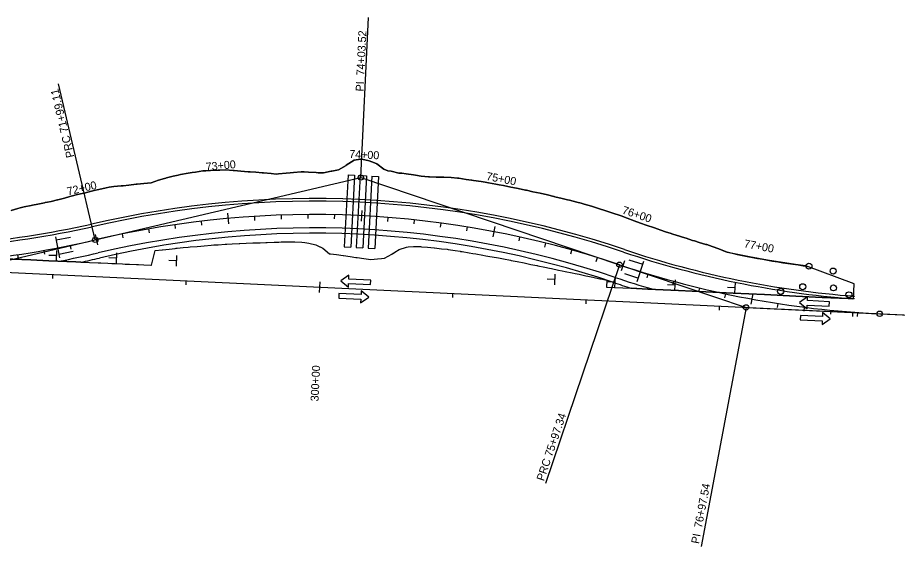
# Model space of a CAD drawing. Extents: x 1140339 to 1165793, y 1646213 to 1669071.
# Drawn here: x 1164666 to 1165325, y 1656552 to 1656948 of the extents above; entities that cross this region are included whole.
import ezdxf

# ---------------------------------------------------------------- set-up
doc = ezdxf.new("R2010")
doc.units = 0
for name, color, linetype in [('Level 47', 7, 'Continuous'), ('R_Horz Alg', 7, 'Continuous'), ('R_Horz Alg Annot', 7, 'Continuous'), ('R_MOT', 7, 'Continuous'), ('R_No Plot', 7, 'Continuous'), ('R_Proposed Const Limits_Fill', 7, 'Continuous'), ('R_Proposed Road_Lane', 7, 'Continuous'), ('R_Proposed Road_Shoulder', 7, 'Continuous'), ('R_Water', 7, 'Continuous')]:
    doc.layers.add(name, color=color, linetype=linetype)

msp = doc.modelspace()

# ---------------------------------------------------------------- linework, layer by layer
at = {"layer": 'Level 47'}
for centre in [(1165258.51, 1656761.83), (1165276.59, 1656758.13), (1165237.3, 1656742.92), (1165253.81, 1656746.4), (1165276.88, 1656745.53), (1165288.44, 1656740.36)]:
    msp.add_circle(centre, 2.25, dxfattribs=at)
at = {"layer": 'R_Horz Alg'}
for p, q in [((1164092.75, 1656783.95), (1165790.84, 1656703.38)), ((1165311.49, 1656726.12), (1165424.02, 1656720.78))]:
    msp.add_line(p, q, dxfattribs=at)
for centre, start, end in [((1164887.48, 1656084.3), 71.35438, 103.21228), ((1164560.09, 1657478.78), 267.28333, 283.21228), ((1165345.43, 1657441.51), 251.35438, 267.28333)]:
    msp.add_arc(centre, 716.2, start, end, dxfattribs=at)
at = {"layer": 'R_Horz Alg Annot'}
for p, q in [((1164723.78, 1656781.54), (1164922.78, 1656828.26)), ((1164922.78, 1656828.26), (1165116.46, 1656762.91)), ((1164626.23, 1656758.64), (1164723.78, 1656781.54)), ((1165116.46, 1656762.91), (1165211.4, 1656730.87)), ((1165211.4, 1656730.87), (1165311.49, 1656726.12))]:
    msp.add_line(p, q, dxfattribs=at)
for points in [[(1164922.78, 1656828.26), (1164928.47, 1656948.12)], [(1164723.78, 1656781.54), (1164696.36, 1656898.36)], [(1164923.4, 1656803.6), (1164923, 1656795.61)], [(1164822.94, 1656801.6), (1164823.66, 1656793.63)], [(1164843.43, 1656796.13), (1164843.24, 1656799.13)], [(1164863.32, 1656797.09), (1164863.22, 1656800.09)], [(1164883.23, 1656797.48), (1164883.21, 1656800.48)], [(1164903.15, 1656797.32), (1164903.21, 1656800.32)], [(1164942.92, 1656795.34), (1164943.16, 1656798.33)], [(1164962.76, 1656793.51), (1164963.07, 1656796.5)], [(1164764.35, 1656786.79), (1164763.84, 1656789.74)], [(1164784.02, 1656789.95), (1164783.58, 1656792.92)], [(1164803.76, 1656792.57), (1164803.41, 1656795.54)], [(1164982.53, 1656791.13), (1164982.93, 1656794.11)], [(1165002.23, 1656788.2), (1165002.71, 1656791.17)], [(1165023.16, 1656791.6), (1165021.65, 1656783.74)], [(1164723.74, 1656785.64), (1164725.56, 1656777.85)], [(1164744.79, 1656783.08), (1164744.19, 1656786.02)], [(1165041.34, 1656780.7), (1165041.99, 1656783.63)], [(1164705.73, 1656774.48), (1164705.12, 1656777.42)], [(1165060.73, 1656776.13), (1165061.45, 1656779.04)], [(1164666.19, 1656767.45), (1164665.75, 1656770.42)], [(1164686.01, 1656770.69), (1164685.48, 1656773.64)], [(1165079.98, 1656771.03), (1165080.79, 1656773.92)], [(1165116.46, 1656762.91), (1165061.11, 1656598.88)], [(1165099.08, 1656765.38), (1165099.97, 1656768.25)], [(1165120.25, 1656765.85), (1165117.72, 1656758.26)], [(1164691.93, 1656752.52), (1164692.07, 1656755.51)], [(1164791.82, 1656747.78), (1164791.96, 1656750.77)], [(1164892.04, 1656750.03), (1164891.66, 1656742.04)], [(1165137.17, 1656753.13), (1165138.04, 1656756)], [(1165156.48, 1656747.58), (1165157.26, 1656750.48)], [(1165175.93, 1656742.58), (1165176.63, 1656745.49)], [(1164991.59, 1656738.3), (1164991.74, 1656741.29)], [(1165091.48, 1656733.56), (1165091.62, 1656736.55)], [(1165195.51, 1656738.12), (1165196.13, 1656741.05)], [(1165216.47, 1656741.09), (1165215.02, 1656733.22)], [(1165211.4, 1656730.87), (1165177.62, 1656551.76)], [(1165191.37, 1656728.82), (1165191.51, 1656731.81)], [(1165235, 1656730.84), (1165235.47, 1656733.81)], [(1165254.89, 1656728.04), (1165255.27, 1656731.01)], [(1165274.85, 1656725.79), (1165275.14, 1656728.77)], [(1165291.26, 1656724.08), (1165291.4, 1656727.07)], [(1165294.86, 1656724.1), (1165295.07, 1656727.09)]]:
    msp.add_lwpolyline(points, dxfattribs=at)
for centre in [(1164922.78, 1656828.26), (1164723.78, 1656781.54), (1165116.46, 1656762.91), (1165211.4, 1656730.87), (1165311.49, 1656726.12)]:
    msp.add_circle(centre, 2, dxfattribs=at)
at = {"layer": 'R_MOT'}
for p, q in [((1164694.07, 1656783.87), (1164697.09, 1656768.16)), ((1164705.29, 1656783.34), (1164694.56, 1656781.28)), ((1164694.5, 1656769.68), (1164689.05, 1656769.9)), ((1164694.79, 1656773.65), (1164694.46, 1656765.66)), ((1164707.34, 1656772.68), (1164696.61, 1656770.62)), ((1164739.76, 1656771.84), (1164739.43, 1656763.85)), ((1164784.72, 1656769.88), (1164784.39, 1656761.89)), ((1164739.48, 1656767.87), (1164734.03, 1656768.1)), ((1164784.44, 1656765.91), (1164778.98, 1656766.13)), ((1165123.65, 1656766.6), (1165134.05, 1656763.25)), ((1165129.91, 1656750.41), (1165134.82, 1656765.64)), ((1165120.33, 1656756.27), (1165130.72, 1656752.92)), ((1165067.94, 1656751.78), (1165062.48, 1656752.01)), ((1165068.22, 1656755.75), (1165067.89, 1656747.76)), ((1165112.95, 1656749.92), (1165107.5, 1656750.15)), ((1165113.23, 1656753.89), (1165112.9, 1656745.9)), ((1165158.15, 1656751.65), (1165157.82, 1656743.65)), ((1165203.13, 1656749.58), (1165202.8, 1656741.58)), ((1165157.87, 1656747.68), (1165152.42, 1656747.9)), ((1165202.85, 1656745.6), (1165197.39, 1656745.83))]:
    msp.add_line(p, q, dxfattribs=at)
for points in [[(1164913.84, 1656754.97), (1164907.79, 1656750.75), (1164913.41, 1656745.98), (1164913.54, 1656748.78), (1164930.07, 1656748), (1164930.23, 1656751.37), (1164913.7, 1656752.16)], [(1164922.6, 1656734.27), (1164928.65, 1656738.49), (1164923.03, 1656743.26), (1164922.89, 1656740.45), (1164906.36, 1656741.23), (1164906.2, 1656737.86), (1164922.73, 1656737.08)], [(1165257.48, 1656738.77), (1165251.43, 1656734.55), (1165257.05, 1656729.78), (1165257.19, 1656732.59), (1165273.72, 1656731.8), (1165273.88, 1656735.17), (1165257.35, 1656735.96)], [(1165268.31, 1656717.99), (1165274.36, 1656722.21), (1165268.73, 1656726.98), (1165268.6, 1656724.17), (1165252.07, 1656724.95), (1165251.91, 1656721.58), (1165268.44, 1656720.8)]]:
    msp.add_lwpolyline(points, close=True, dxfattribs=at)
at = {"layer": 'R_No Plot'}
msp.add_line((1164947.09, 1656771.47), (1164947.12, 1656771.49), dxfattribs=at)
for points in [[(1165197.25, 1656772.27), (1165190.97, 1656774.87), (1165190.93, 1656774.89), (1165186.07, 1656776.65), (1165181.89, 1656777.93), (1165181.15, 1656778.16), (1165176.21, 1656779.58), (1165172.74, 1656780.68), (1165171.31, 1656781.14), (1165166.43, 1656782.74), (1165163.65, 1656783.59), (1165161.52, 1656784.21), (1165156.62, 1656785.75), (1165154.55, 1656786.42), (1165154.45, 1656786.46), (1165151.75, 1656787.35), (1165146.89, 1656788.98), (1165145.52, 1656789.46), (1165142.04, 1656790.67), (1165137.2, 1656792.34), (1165136.52, 1656792.58), (1165132.37, 1656794.05), (1165127.55, 1656795.77), (1165127.55, 1656795.77), (1165127.54, 1656795.77), (1165122.26, 1656797.77), (1165117.72, 1656799.43), (1165116.96, 1656799.7), (1165111.62, 1656801.54), (1165107.79, 1656802.85), (1165106.27, 1656803.36), (1165100.9, 1656805.11), (1165097.79, 1656806.02), (1165095.48, 1656806.72), (1165090.07, 1656808.35), (1165087.73, 1656809.04), (1165084.62, 1656809.83), (1165079.15, 1656811.22), (1165077.56, 1656811.63), (1165073.67, 1656812.6), (1165068.17, 1656813.88), (1165067.55, 1656814.02), (1165067.35, 1656814.07), (1165062.67, 1656815.16), (1165057.16, 1656816.41), (1165057.12, 1656816.42), (1165051.64, 1656817.62), (1165046.87, 1656818.65), (1165046.12, 1656818.81), (1165040.6, 1656819.97), (1165036.6, 1656820.8), (1165035.07, 1656821.11), (1165029.53, 1656822.23), (1165026.31, 1656822.86), (1165023.99, 1656823.3), (1165018.43, 1656824.32), (1165015.99, 1656824.75), (1165012.87, 1656825.27), (1165007.28, 1656826.09), (1165006.04, 1656826.27), (1165005.62, 1656826.33), (1165001.69, 1656826.88), (1164996.1, 1656827.65), (1164995.22, 1656827.76), (1164990.5, 1656828.35), (1164984.83, 1656828.55), (1164984.75, 1656828.55), (1164979.16, 1656828.61), (1164974.21, 1656828.65), (1164973.49, 1656828.65), (1164967.89, 1656829.25), (1164963.83, 1656830.02), (1164962.34, 1656830.29), (1164956.76, 1656831.13), (1164953.45, 1656831.42), (1164951.14, 1656831.62), (1164945.6, 1656833), (1164943.09, 1656833.31), (1164940.05, 1656834.6), (1164934.64, 1656838.59), (1164932.95, 1656839.35), (1164929.07, 1656840.82), (1164923.44, 1656842.08), (1164923.43, 1656842.07), (1164922.49, 1656841.92), (1164917.69, 1656841.17), (1164911.88, 1656837.41), (1164911.75, 1656837.29), (1164906.13, 1656834.12), (1164901.15, 1656833.13), (1164900.48, 1656832.99), (1164894.84, 1656831.73), (1164890.69, 1656831.8), (1164889.22, 1656831.89), (1164883.6, 1656832.24), (1164880.24, 1656832.44), (1164877.98, 1656832.47), (1164872.37, 1656832.01), (1164869.81, 1656831.77), (1164866.76, 1656831.47), (1164861.16, 1656830.9), (1164859.4, 1656830.86), (1164855.53, 1656831.16), (1164849.88, 1656831.76), (1164848.9, 1656831.86), (1164844.21, 1656832.33), (1164839.81, 1656832.51), (1164838.55, 1656832.56), (1164838.38, 1656832.57), (1164832.87, 1656833.01), (1164827.81, 1656833.47), (1164827.17, 1656833.53), (1164821.46, 1656834.02), (1164817.24, 1656833.8), (1164815.8, 1656833.74), (1164810.15, 1656833.46), (1164806.72, 1656833.27), (1164804.49, 1656833.14), (1164798.88, 1656832.37), (1164796.3, 1656831.89), (1164793.28, 1656831.5), (1164787.71, 1656830.47), (1164785.93, 1656830.11), (1164782.16, 1656829.33), (1164777.27, 1656828.01), (1164776.67, 1656827.82), (1164775.67, 1656827.62), (1164771.18, 1656826.36), (1164765.79, 1656824.33), (1164765.58, 1656824.32), (1164760.16, 1656823.85), (1164760.14, 1656823.85), (1164755.11, 1656823.38), (1164754.52, 1656823.32), (1164748.95, 1656822.45), (1164744.68, 1656822.09), (1164743.29, 1656821.97), (1164737.63, 1656821.45), (1164734.21, 1656820.93), (1164732.06, 1656820.5), (1164726.54, 1656819.26), (1164723.95, 1656818.66), (1164721.04, 1656817.97), (1164715.55, 1656816.63), (1164715.55, 1656816.63), (1164713.91, 1656816.25), (1164710.57, 1656815.47), (1164705.62, 1656814.16), (1164704.7, 1656813.91), (1164700.67, 1656812.87), (1164695.71, 1656811.6), (1164695.49, 1656811.54), (1164690.74, 1656810.39), (1164687.95, 1656809.8), (1164686.21, 1656809.44), (1164685.73, 1656809.34), (1164680.71, 1656808.33), (1164676.88, 1656807.58), (1164675.68, 1656807.35), (1164670.65, 1656806.38), (1164667.57, 1656805.55), (1164665.68, 1656805.05), (1164660.72, 1656803.55)], [(1164713.11, 1656764.79), (1164725.97, 1656764.29), (1164727.85, 1656764.22), (1164727.85, 1656764.22), (1164733.28, 1656763.99), (1164736.15, 1656763.86), (1164738.7, 1656763.75), (1164744.09, 1656763.52), (1164746.17, 1656763.42), (1164749.46, 1656763.28), (1164754.81, 1656763.05), (1164756.12, 1656762.99), (1164760.14, 1656762.81), (1164765.45, 1656762.58), (1164766, 1656762.56), (1164768.79, 1656773.63), (1164768.8, 1656773.64), (1164773.85, 1656774.12), (1164774.05, 1656774.14), (1164779.28, 1656774.67), (1164783.57, 1656775.12), (1164784.51, 1656775.21), (1164785.09, 1656775.27), (1164789.74, 1656775.73), (1164793.29, 1656776.02), (1164794.97, 1656776.18), (1164800.2, 1656776.66), (1164803, 1656776.91), (1164805.42, 1656777.12), (1164810.65, 1656777.54), (1164812.72, 1656777.69), (1164815.88, 1656777.89), (1164821.11, 1656778.21), (1164822.44, 1656778.29), (1164826.35, 1656778.5), (1164831.58, 1656778.76), (1164832.16, 1656778.79), (1164836.81, 1656778.99), (1164841.88, 1656779.19), (1164842.04, 1656779.19), (1164843.2, 1656779.23), (1164847.27, 1656779.39), (1164851.6, 1656779.57), (1164852.5, 1656779.61), (1164857.73, 1656779.79), (1164861.32, 1656779.88), (1164862.96, 1656779.93), (1164868.18, 1656780.06), (1164871.03, 1656780.1), (1164873.41, 1656780.13), (1164878.65, 1656779.73), (1164880.76, 1656779.55), (1164883.88, 1656779.17), (1164889.1, 1656777.81), (1164890.45, 1656777.13), (1164893.26, 1656775.72)], [(1164947.12, 1656771.49), (1164948.22, 1656772.26), (1164951.47, 1656774.19), (1164956.9, 1656776.11), (1164958.32, 1656776.22), (1164962.2, 1656776.57), (1164967.46, 1656776.46), (1164968.12, 1656776.4), (1164972.67, 1656775.97), (1164977.81, 1656775.45), (1164977.88, 1656775.44), (1164983.09, 1656774.89), (1164987.49, 1656774.43), (1164988.31, 1656774.35), (1164993.48, 1656773.5), (1164997.12, 1656772.94), (1164997.51, 1656772.88), (1164998.66, 1656772.7), (1165003.83, 1656771.87), (1165006.73, 1656771.39), (1165008.99, 1656770.97), (1165014.15, 1656770.05), (1165016.31, 1656769.67), (1165019.31, 1656769.14), (1165024.47, 1656768.19), (1165025.9, 1656767.93), (1165029.62, 1656767.24), (1165034.77, 1656766.26), (1165035.47, 1656766.13), (1165039.93, 1656765.28), (1165045.03, 1656764.23), (1165045.06, 1656764.22), (1165050.2, 1656763.16), (1165054.59, 1656762.28), (1165054.77, 1656762.24), (1165055.35, 1656762.13), (1165060.5, 1656761.07), (1165064.15, 1656760.32), (1165065.64, 1656760), (1165070.78, 1656758.91), (1165073.71, 1656758.3), (1165075.94, 1656757.85), (1165081.11, 1656756.8), (1165083.31, 1656756.34), (1165086.28, 1656755.73), (1165091.45, 1656754.66), (1165092.92, 1656754.35), (1165096.62, 1656753.56), (1165101.79, 1656752.41), (1165102.53, 1656752.25), (1165106.95, 1656751.22), (1165106.71, 1656746.14)], [(1164526.64, 1656773.85), (1164548.55, 1656772.67), (1164580.97, 1656770.94), (1164594.5, 1656770.34), (1164608.03, 1656769.75), (1164621.57, 1656769.15), (1164635.1, 1656768.56), (1164648.58, 1656767.85), (1164662.05, 1656767.15), (1164675.52, 1656766.44), (1164689, 1656765.74), (1164709.14, 1656764.95), (1164713.11, 1656764.79)], [(1164893.26, 1656775.72), (1164894.28, 1656775.2), (1164899.4, 1656771.16), (1164900.02, 1656771.08), (1164904.55, 1656770.52), (1164909.57, 1656769.84), (1164909.69, 1656769.82), (1164914.82, 1656769.05), (1164919.09, 1656768.37), (1164919.93, 1656768.24), (1164919.93, 1656768.24), (1164925.04, 1656767.5), (1164928.59, 1656767), (1164930.15, 1656766.77), (1164935.34, 1656767.28), (1164938.21, 1656767.67), (1164940.54, 1656767.88), (1164945.95, 1656770.68), (1164947.09, 1656771.47)], [(1165291.88, 1656737.33), (1165292.42, 1656748.62), (1165256.26, 1656761.94), (1165248.42, 1656762.96), (1165227.47, 1656766.29), (1165213.89, 1656768.8), (1165200.33, 1656771.6), (1165197.25, 1656772.27)], [(1165106.71, 1656746.14), (1165125.12, 1656745.35)], [(1165125.12, 1656745.35), (1165137.88, 1656744.66), (1165160.78, 1656743.52), (1165181.21, 1656742.58), (1165201.64, 1656741.64), (1165225.13, 1656740.47), (1165248.62, 1656739.31), (1165268.29, 1656738.43), (1165287.96, 1656737.55), (1165291.88, 1656737.33)]]:
    msp.add_lwpolyline(points, dxfattribs=at)
at = {"layer": 'R_Proposed Const Limits_Fill'}
for points in [[(1164660.72, 1656803.55), (1164665.68, 1656805.05), (1164667.57, 1656805.55), (1164670.65, 1656806.38), (1164675.68, 1656807.35), (1164676.88, 1656807.58), (1164680.71, 1656808.33), (1164685.73, 1656809.34), (1164686.21, 1656809.44), (1164687.95, 1656809.8), (1164690.74, 1656810.39), (1164695.49, 1656811.54), (1164695.71, 1656811.6), (1164700.67, 1656812.87), (1164704.7, 1656813.91), (1164705.62, 1656814.16), (1164710.57, 1656815.47), (1164713.91, 1656816.25), (1164715.55, 1656816.63), (1164715.55, 1656816.63), (1164721.04, 1656817.97), (1164723.95, 1656818.66), (1164726.54, 1656819.26), (1164732.06, 1656820.5), (1164734.21, 1656820.93), (1164737.63, 1656821.45), (1164743.29, 1656821.97), (1164744.68, 1656822.09), (1164748.95, 1656822.45), (1164754.52, 1656823.32), (1164755.11, 1656823.38), (1164760.14, 1656823.85), (1164760.16, 1656823.85), (1164765.58, 1656824.32), (1164765.79, 1656824.33), (1164771.18, 1656826.36), (1164775.67, 1656827.62), (1164776.67, 1656827.82), (1164777.27, 1656828.01), (1164782.16, 1656829.33), (1164785.93, 1656830.11), (1164787.71, 1656830.47), (1164793.28, 1656831.5), (1164796.3, 1656831.89), (1164798.88, 1656832.37), (1164804.49, 1656833.14), (1164806.72, 1656833.27), (1164810.15, 1656833.46), (1164815.8, 1656833.74), (1164817.24, 1656833.8), (1164821.46, 1656834.02), (1164827.17, 1656833.53), (1164827.81, 1656833.47), (1164832.87, 1656833.01), (1164838.38, 1656832.57), (1164838.55, 1656832.56), (1164839.81, 1656832.51), (1164844.21, 1656832.33), (1164848.9, 1656831.86), (1164849.88, 1656831.76), (1164855.53, 1656831.16), (1164859.4, 1656830.86), (1164861.16, 1656830.9), (1164866.76, 1656831.47), (1164869.81, 1656831.77), (1164872.37, 1656832.01), (1164877.98, 1656832.47), (1164880.24, 1656832.44), (1164883.6, 1656832.24), (1164889.22, 1656831.89), (1164890.69, 1656831.8), (1164894.84, 1656831.73), (1164900.48, 1656832.99), (1164901.15, 1656833.13), (1164906.13, 1656834.12), (1164911.75, 1656837.29), (1164911.88, 1656837.41), (1164917.69, 1656841.17), (1164922.49, 1656841.92), (1164923.43, 1656842.07), (1164923.44, 1656842.08), (1164929.07, 1656840.82), (1164932.95, 1656839.35), (1164934.64, 1656838.59), (1164940.05, 1656834.6), (1164943.09, 1656833.31), (1164945.6, 1656833), (1164951.14, 1656831.62), (1164953.45, 1656831.42), (1164956.76, 1656831.13), (1164962.34, 1656830.29), (1164963.83, 1656830.02), (1164967.89, 1656829.25), (1164973.49, 1656828.65), (1164974.21, 1656828.65), (1164979.16, 1656828.61), (1164984.75, 1656828.55), (1164984.83, 1656828.55), (1164990.5, 1656828.35), (1164995.22, 1656827.76), (1164996.1, 1656827.65), (1165001.69, 1656826.88), (1165005.62, 1656826.33), (1165006.04, 1656826.27), (1165007.28, 1656826.09), (1165012.87, 1656825.27), (1165015.99, 1656824.75), (1165018.43, 1656824.32), (1165023.99, 1656823.3), (1165026.31, 1656822.86), (1165029.53, 1656822.23), (1165035.07, 1656821.11), (1165036.6, 1656820.8), (1165040.6, 1656819.97), (1165046.12, 1656818.81), (1165046.87, 1656818.65), (1165051.64, 1656817.62), (1165057.12, 1656816.42), (1165057.16, 1656816.41), (1165062.67, 1656815.16), (1165067.35, 1656814.07), (1165067.55, 1656814.02), (1165068.17, 1656813.88), (1165073.67, 1656812.6), (1165077.56, 1656811.63), (1165079.15, 1656811.22), (1165084.62, 1656809.83), (1165087.73, 1656809.04), (1165090.07, 1656808.35), (1165095.48, 1656806.72), (1165097.79, 1656806.02), (1165100.9, 1656805.11), (1165106.27, 1656803.36), (1165107.79, 1656802.85), (1165111.62, 1656801.54), (1165116.96, 1656799.7), (1165117.72, 1656799.43), (1165122.26, 1656797.77), (1165127.54, 1656795.77), (1165127.55, 1656795.77), (1165127.55, 1656795.77), (1165132.37, 1656794.05), (1165136.52, 1656792.58), (1165137.2, 1656792.34), (1165142.04, 1656790.67), (1165145.52, 1656789.46), (1165146.89, 1656788.98), (1165151.75, 1656787.35), (1165154.45, 1656786.46), (1165154.55, 1656786.42), (1165156.62, 1656785.75), (1165161.52, 1656784.21), (1165163.65, 1656783.59), (1165166.43, 1656782.74), (1165171.31, 1656781.14), (1165172.74, 1656780.68), (1165176.21, 1656779.58), (1165181.15, 1656778.16), (1165181.89, 1656777.93), (1165186.07, 1656776.65), (1165190.93, 1656774.89), (1165190.97, 1656774.87), (1165195.75, 1656772.89), (1165197.25, 1656772.27)], [(1164713.11, 1656764.79), (1164725.97, 1656764.29), (1164727.85, 1656764.22), (1164727.85, 1656764.22), (1164733.28, 1656763.99), (1164736.15, 1656763.86), (1164738.7, 1656763.75), (1164744.09, 1656763.52), (1164746.17, 1656763.42), (1164749.46, 1656763.28), (1164754.81, 1656763.05), (1164756.12, 1656762.99), (1164760.14, 1656762.81), (1164765.45, 1656762.58), (1164766, 1656762.56), (1164768.79, 1656773.63), (1164768.8, 1656773.64), (1164773.85, 1656774.12), (1164774.05, 1656774.14), (1164779.28, 1656774.67), (1164783.57, 1656775.12), (1164784.51, 1656775.21), (1164785.09, 1656775.27), (1164789.74, 1656775.73), (1164793.29, 1656776.02), (1164794.97, 1656776.18), (1164800.2, 1656776.66), (1164803, 1656776.91), (1164805.42, 1656777.12), (1164810.65, 1656777.54), (1164812.72, 1656777.69), (1164815.88, 1656777.89), (1164821.11, 1656778.21), (1164822.44, 1656778.29), (1164826.35, 1656778.5), (1164831.58, 1656778.76), (1164832.16, 1656778.79), (1164836.81, 1656778.99), (1164841.88, 1656779.19), (1164842.04, 1656779.19), (1164843.2, 1656779.23), (1164847.27, 1656779.39), (1164851.6, 1656779.57), (1164852.5, 1656779.61), (1164857.73, 1656779.79), (1164861.32, 1656779.88), (1164862.96, 1656779.93), (1164868.18, 1656780.06), (1164871.03, 1656780.1), (1164873.41, 1656780.13), (1164878.65, 1656779.73), (1164880.76, 1656779.55), (1164883.88, 1656779.17), (1164889.1, 1656777.81), (1164890.45, 1656777.13), (1164894.28, 1656775.2), (1164899.4, 1656771.16), (1164900.02, 1656771.08), (1164904.55, 1656770.52), (1164909.57, 1656769.84), (1164909.69, 1656769.82), (1164914.82, 1656769.05), (1164919.09, 1656768.37), (1164919.93, 1656768.24), (1164919.93, 1656768.24), (1164925.04, 1656767.5), (1164928.59, 1656767), (1164930.15, 1656766.77), (1164935.34, 1656767.28), (1164938.21, 1656767.67), (1164940.54, 1656767.88), (1164945.95, 1656770.68), (1164948.22, 1656772.26), (1164951.47, 1656774.19), (1164956.9, 1656776.11), (1164958.32, 1656776.22), (1164962.2, 1656776.57), (1164967.46, 1656776.46), (1164968.12, 1656776.4), (1164972.67, 1656775.97), (1164977.81, 1656775.45), (1164977.88, 1656775.44), (1164983.09, 1656774.89), (1164987.49, 1656774.43), (1164988.31, 1656774.35), (1164993.48, 1656773.5), (1164997.12, 1656772.94), (1164997.51, 1656772.88), (1164998.66, 1656772.7), (1165003.83, 1656771.87), (1165006.73, 1656771.39), (1165008.99, 1656770.97), (1165014.15, 1656770.05), (1165016.31, 1656769.67), (1165019.31, 1656769.14), (1165024.47, 1656768.19), (1165025.9, 1656767.93), (1165029.62, 1656767.24), (1165034.77, 1656766.26), (1165035.47, 1656766.13), (1165039.93, 1656765.28), (1165045.03, 1656764.23), (1165045.06, 1656764.22), (1165050.2, 1656763.16), (1165054.59, 1656762.28), (1165054.77, 1656762.24), (1165055.35, 1656762.13), (1165060.5, 1656761.07), (1165064.15, 1656760.32), (1165065.64, 1656760), (1165070.78, 1656758.91), (1165073.71, 1656758.3), (1165075.94, 1656757.85), (1165081.11, 1656756.8), (1165083.31, 1656756.34), (1165086.28, 1656755.73), (1165091.45, 1656754.66), (1165092.92, 1656754.35), (1165096.62, 1656753.56), (1165101.79, 1656752.41), (1165102.53, 1656752.25), (1165106.95, 1656751.22), (1165106.71, 1656746.14)], [(1165106.71, 1656746.15), (1165125.12, 1656745.35)]]:
    msp.add_lwpolyline(points, dxfattribs=at)
msp.add_arc((1165345.43, 1657441.51), 685.45, 257.51481, 262.66543, dxfattribs=at)
at = {"layer": 'R_Proposed Road_Lane'}
for points in [[(1164713.11, 1656764.79), (1164709.14, 1656764.95), (1164689, 1656765.74), (1164675.52, 1656766.44), (1164662.05, 1656767.15), (1164648.58, 1656767.85), (1164635.1, 1656768.56), (1164621.57, 1656769.15), (1164608.03, 1656769.75), (1164594.5, 1656770.34), (1164580.97, 1656770.94), (1164548.55, 1656772.67), (1164526.64, 1656773.85)], [(1165292.73, 1656737.28), (1165287.96, 1656737.55), (1165268.29, 1656738.43), (1165248.62, 1656739.31), (1165225.13, 1656740.47), (1165201.64, 1656741.64), (1165181.21, 1656742.58), (1165160.78, 1656743.52), (1165137.88, 1656744.66), (1165125.31, 1656745.28)]]:
    msp.add_lwpolyline(points, dxfattribs=at)
for centre, radius, start, end in [((1164887.48, 1656084.3), 726.2, 71.35438, 103.21228), ((1164553.87, 1657567.66), 794.27, 268.03532, 282.1838), ((1164887.48, 1656084.3), 706.2, 71.35438, 103.21228), ((1164560.09, 1657478.78), 726.2, 280.80499, 283.21228), ((1165345.43, 1657441.51), 706.2, 251.35438, 265.59591), ((1165345.43, 1657441.51), 726.2, 251.35438, 253.71097)]:
    msp.add_arc(centre, radius, start, end, dxfattribs=at)
at = {"layer": 'R_Proposed Road_Shoulder'}
for centre, radius, start, end in [((1164887.48, 1656084.3), 728.2, 71.35438, 103.21228), ((1164553.87, 1657567.66), 792.27, 268.03532, 282.1838), ((1164887.48, 1656084.3), 702.2, 71.35438, 103.21228), ((1165345.43, 1657441.51), 704.2, 251.35438, 265.7202), ((1164560.09, 1657478.78), 730.2, 282.09683, 283.21228), ((1165345.43, 1657441.51), 730.2, 251.35438, 252.45513)]:
    msp.add_arc(centre, radius, start, end, dxfattribs=at)
at = {"layer": 'R_Water'}
for p, q in [((1164913.15, 1656830.19), (1164910.28, 1656776.26)), ((1164913.15, 1656830.19), (1164918.14, 1656829.92)), ((1164918.14, 1656829.92), (1164915.27, 1656776)), ((1164922.14, 1656829.71), (1164919.27, 1656775.78)), ((1164922.14, 1656829.71), (1164927.13, 1656829.44)), ((1164927.13, 1656829.44), (1164924.26, 1656775.52)), ((1164931.12, 1656829.23), (1164928.26, 1656775.31)), ((1164931.12, 1656829.23), (1164936.12, 1656828.96)), ((1164936.12, 1656828.96), (1164933.25, 1656775.04)), ((1164910.28, 1656776.26), (1164915.27, 1656776)), ((1164919.27, 1656775.78), (1164924.26, 1656775.52)), ((1164928.26, 1656775.31), (1164933.25, 1656775.04))]:
    msp.add_line(p, q, dxfattribs=at)

# ---------------------------------------------------------------- texts
at = {"layer": 'R_Horz Alg Annot'}
for s, rotation, p in [('PI  74+03.52', 87.28333, (1164924.83, 1656892.63)), ('PRC 71+99.11', 103.21228, (1164708.14, 1656843.82)), ('74+00', 357.14123, (1164913.93, 1656842.98)), ('73+00', 5.14123, (1164806.83, 1656833.28)), ('75+00', 349.14123, (1165016.4, 1656826.5)), ('72+00', 13.14123, (1164703.38, 1656814.77)), ('76+00', 341.56753, (1165118.02, 1656801.38)), ('77+00', 349.56753, (1165209.46, 1656775.93)), ('300+00', 87.28333, (1164891.03, 1656660.37)), ('PRC 75+97.34', 71.35438, (1165059.88, 1656600.35)), ('PI  76+97.54', 79.31886, (1165176.05, 1656553.38))]:
    msp.add_text(s, height=6, rotation=rotation, dxfattribs=at).set_placement(p)

doc.saveas('drawing.dxf')
